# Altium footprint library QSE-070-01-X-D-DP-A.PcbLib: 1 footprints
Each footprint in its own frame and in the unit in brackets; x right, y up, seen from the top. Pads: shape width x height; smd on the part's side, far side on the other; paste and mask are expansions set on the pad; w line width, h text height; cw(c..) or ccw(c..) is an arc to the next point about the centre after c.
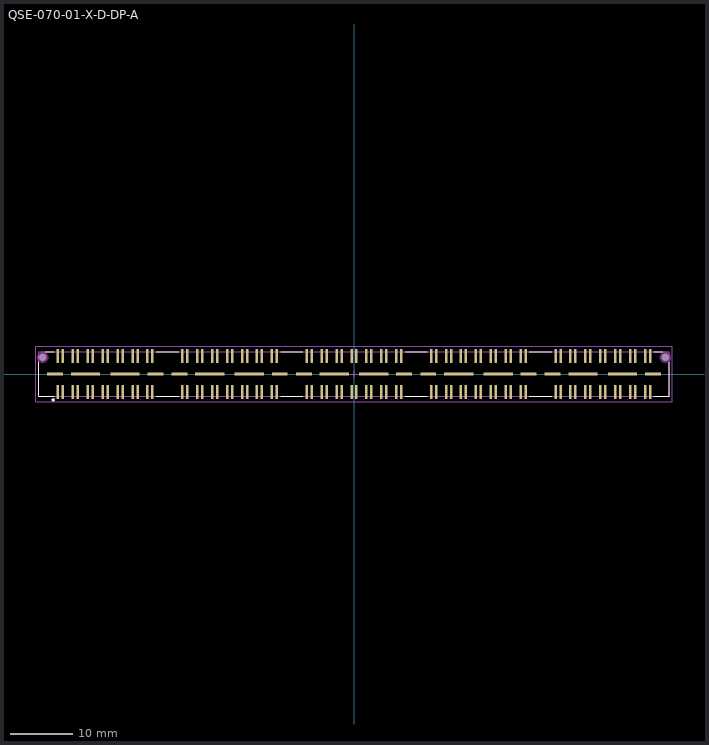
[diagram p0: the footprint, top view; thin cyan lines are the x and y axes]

## QSE-070-01-X-D-DP-A [mm] "0.80mm pitch, 140 pin, high speed socket strip; differential"
height 3.25
pads (162):
  rect 0.4x2.25 smd mask+0: 1(-47.6,-2.87) 2(-47.6,2.87) 3(-46.8,-2.87) 4(-46.8,2.87) 5(-45.2,-2.87) 6(-45.2,2.87) 7(-44.4,-2.87) 8(-44.4,2.87) 9(-42.8,-2.87) 10(-42.8,2.87) 11(-42,-2.87) 12(-42,2.87) 13(-40.4,-2.87) 14(-40.4,2.87) 15(-39.6,-2.87) 16(-39.6,2.87) 17(-38,-2.87) 18(-38,2.87) 19(-37.2,-2.87) 20(-37.2,2.87) 21(-35.6,-2.87) 22(-35.6,2.87) 23(-34.8,-2.87) 24(-34.8,2.87) 25(-33.2,-2.87) 26(-33.2,2.87) 27(-32.4,-2.87) 28(-32.4,2.87) 29(-27.6,-2.87) 30(-27.6,2.87) 31(-26.8,-2.87) 32(-26.8,2.87) 33(-25.2,-2.87) 34(-25.2,2.87) 35(-24.4,-2.87) 36(-24.4,2.87) 37(-22.8,-2.87) 38(-22.8,2.87) 39(-22,-2.87) 40(-22,2.87) 41(-20.4,-2.87) 42(-20.4,2.87) 43(-19.6,-2.87) 44(-19.6,2.87) 45(-18,-2.87) 46(-18,2.87) 47(-17.2,-2.87) 48(-17.2,2.87) 49(-15.6,-2.87) 50(-15.6,2.87) 51(-14.8,-2.87) 52(-14.8,2.87) 53(-13.2,-2.87) 54(-13.2,2.87) 55(-12.4,-2.87) 56(-12.4,2.87) 57(-7.6,-2.87) 58(-7.6,2.87) 59(-6.8,-2.87) 60(-6.8,2.87) 61(-5.2,-2.87) 62(-5.2,2.87) 63(-4.4,-2.87) 64(-4.4,2.87) 65(-2.8,-2.87) 66(-2.8,2.87) 67(-2,-2.87) 68(-2,2.87) 69(-0.4,-2.87) 70(-0.4,2.87) 71(0.4,-2.87) 72(0.4,2.87) 73(2,-2.87) 74(2,2.87) 75(2.8,-2.87) 76(2.8,2.87) 77(4.4,-2.87) 78(4.4,2.87) 79(5.2,-2.87) 80(5.2,2.87) 81(6.8,-2.87) 82(6.8,2.87) 83(7.6,-2.87) 84(7.6,2.87) 85(12.4,-2.87) 86(12.4,2.87) 87(13.2,-2.87) 88(13.2,2.87) 89(14.8,-2.87) 90(14.8,2.87) 91(15.6,-2.87) 92(15.6,2.87) 93(17.2,-2.87) 94(17.2,2.87) 95(18,-2.87) 96(18,2.87) 97(19.6,-2.87) 98(19.6,2.87) 99(20.4,-2.87) 100(20.4,2.87) 101(22,-2.87) 102(22,2.87) 103(22.8,-2.87) 104(22.8,2.87) 105(24.4,-2.87) 106(24.4,2.87) 107(25.2,-2.87) 108(25.2,2.87) 109(26.8,-2.87) 110(26.8,2.87) 111(27.6,-2.87) 112(27.6,2.87) 113(32.4,-2.87) 114(32.4,2.87) 115(33.2,-2.87) 116(33.2,2.87) 117(34.8,-2.87) 118(34.8,2.87) 119(35.6,-2.87) 120(35.6,2.87) 121(37.2,-2.87) 122(37.2,2.87) 123(38,-2.87) 124(38,2.87) 125(39.6,-2.87) 126(39.6,2.87) 127(40.4,-2.87) 128(40.4,2.87) 129(42,-2.87) 130(42,2.87) 131(42.8,-2.87) 132(42.8,2.87) 133(44.4,-2.87) 134(44.4,2.87) 135(45.2,-2.87) 136(45.2,2.87) 137(46.8,-2.87) 138(46.8,2.87) 139(47.6,-2.87) 140(47.6,2.87)
  rect 2.55x0.45 smd mask+0: 141(-48.065,0) 144(-31.935,0) 145(-28.065,0) 148(-11.935,0) 149(-8.065,0) 152(8.065,0) 153(11.935,0) 156(28.065,0) 157(31.935,0) 160(48.065,0)
  rect 4.7x0.45 smd mask+0: 142(-43.175,0) 143(-36.825,0) 146(-23.175,0) 147(-16.825,0) 150(-3.175,0) 151(3.175,0) 154(16.825,0) 155(23.175,0) 158(36.825,0) 159(43.175,0)
  round 1 hole 1.2 unplated mask+0: 161(-50.065,2.67) 162(50.065,2.67)
Top Overlay:
  circle w0.25: c-48.35,-4.15 r0.125
  lines w0.2: -50.65,1.85 -50.65,-3.6 -48.2,-3.6 ; -49.6,3.6 -48.2,3.6 ; -31.8,-3.6 -28.2,-3.6 ; -31.8,3.6 -28.2,3.6 ; -11.8,-3.6 -8.2,-3.6 ; -11.8,3.6 -8.2,3.6 ; 8.2,-3.6 11.8,-3.6 ; 8.2,3.6 11.8,3.6 ; 28.2,-3.6 31.8,-3.6 ; 28.2,3.6 31.8,3.6 ; 48.2,-3.6 50.65,-3.6 50.65,1.85 ; 48.2,3.6 49.6,3.6
Keep-Out Layer:
  pour cut-out: -49.157,2.67 -49.188,2.905 -49.279,3.124 -49.423,3.312 -49.611,3.456 -49.83,3.547 -50.065,3.578 -50.3,3.547 -50.519,3.456 -50.707,3.312 -50.851,3.124 -50.942,2.905 -50.973,2.67 -50.942,2.435 -50.851,2.216 -50.707,2.028 -50.519,1.884 -50.3,1.793 -50.065,1.762 -49.83,1.793 -49.611,1.884 -49.423,2.028 -49.279,2.216 -49.188,2.435
  pour cut-out: 50.973,2.67 50.942,2.905 50.851,3.124 50.707,3.312 50.519,3.456 50.3,3.547 50.065,3.578 49.83,3.547 49.611,3.456 49.423,3.312 49.279,3.124 49.188,2.905 49.157,2.67 49.188,2.435 49.279,2.216 49.423,2.028 49.611,1.884 49.83,1.793 50.065,1.762 50.3,1.793 50.519,1.884 50.707,2.028 50.851,2.216 50.942,2.435
Mechanical 12:
  lines w0.001: -50.65,-3.6 50.65,-3.6 50.65,3.6 -50.65,3.6 -50.65,-3.6
Mechanical 13:
  circle w0.25: c-48.35,-4.15 r0.125
  lines w0.1: -50.65,-3.6 50.65,-3.6 50.65,3.6 -50.65,3.6 -50.65,-3.6
  text ".Designator" at 0,0 h1.52
Mechanical 15:
  lines w0.05: -0.5,0 0.5,0 ; 0,-0.5 0,0.5 ; -51.15,-4.5 51.15,-4.5 51.15,4.5 -51.15,4.5 -51.15,-4.5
